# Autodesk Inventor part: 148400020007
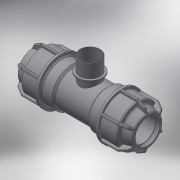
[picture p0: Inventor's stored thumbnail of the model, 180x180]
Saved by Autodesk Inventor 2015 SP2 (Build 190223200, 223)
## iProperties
Created: 2017-08
Part Number: 148400020007
Material: Generic
Description: PLASSON L.14 TEE MALE ADAPTOR (SILVER) 20-3/4"-20
Document SubType Name: Modeling
Designer: KIM
Density: 1 g/cm^3
Appearance: Default
Author: KIM
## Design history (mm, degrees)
derived "148400.ipt"
feature "Solid1::148400.ipt"
feature "Solid2::148400.ipt"
tag "TaggingFeature1"
body "Solid1"
body "Solid2"
other parameters: "d2" = 44, "d4" = 15 deg, "d5" = 29.04, "d6" = 9.5832, "d10" = 42, "d16" = 20.4, "d17" = 2.2, "d22" = 32, "d24" = 2.2, "d25" = 37.8, "d26" = 31.5, "d27" = 2.2, "d28" = 135 deg, "d29" = 1.32, "d31" = 1, "d46" = 150 deg, "d49" = 2.1, "d50" = 0, "d58" = 0.6, "d61" = 360 deg, "d63" = 18, "d64" = 56.5, "d80" = 28.8, "d81" = 1.6, "d84" = 2.2, "d94" = 45, "d96" = 26.441, "d108" = 0.6, "d111" = 0, "d113" = 18, "d114" = 31.7292, "d115" = 18, "d116" = 1.8, "d117" = 26.441, "R_" = 26.441, "E_" = 42, "H_" = 113, "l_" = 44, "l_2" = 18, "A_" = 45
